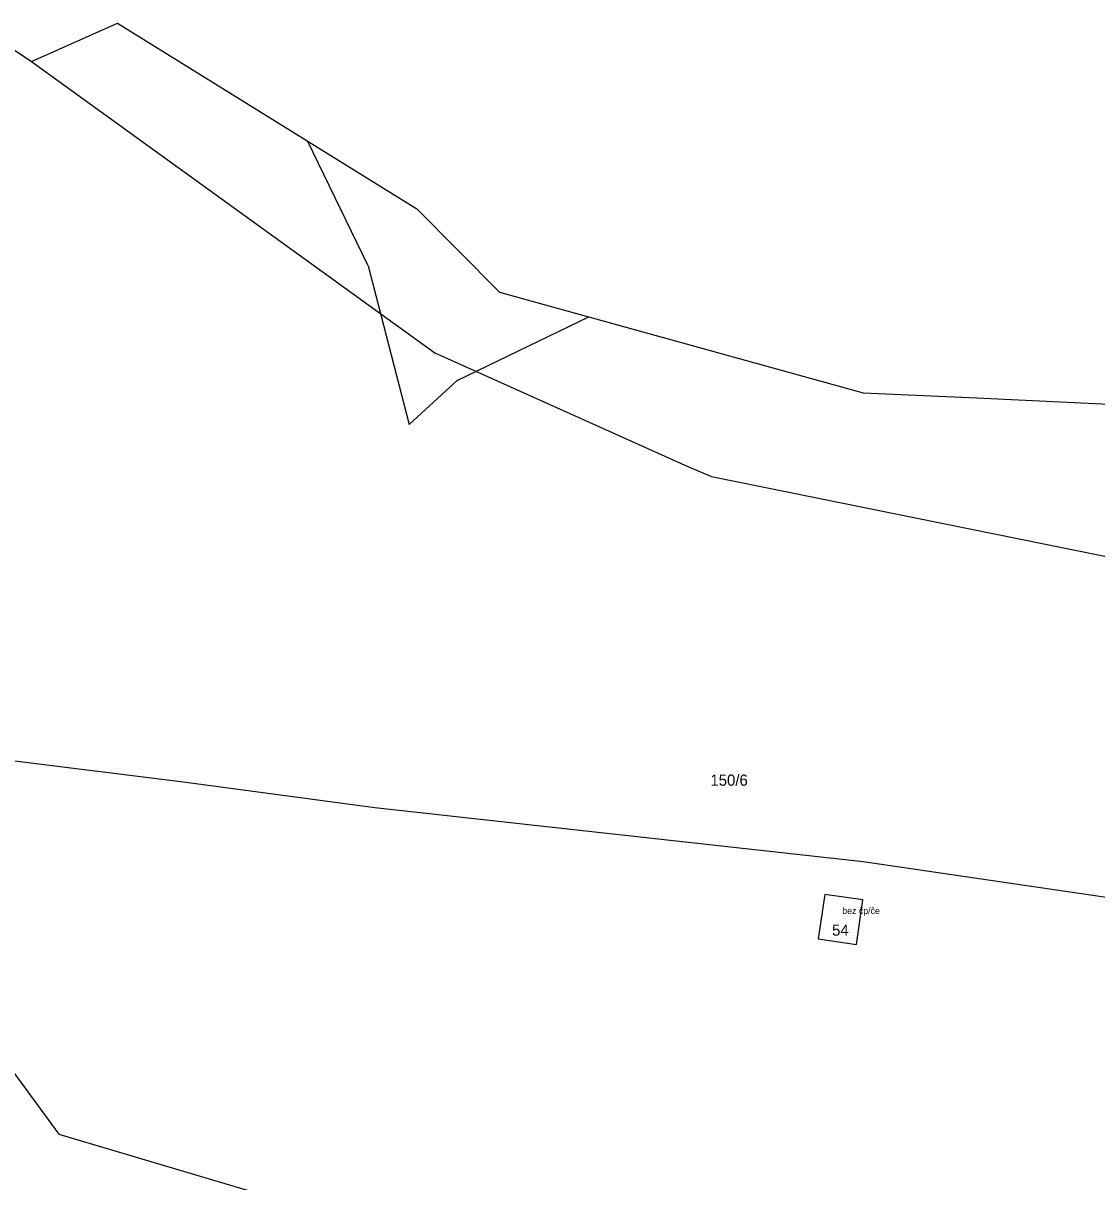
# Model space of a CAD drawing. Extents: x -882150 to -879379, y -1022570 to -1019819.
# Drawn here: x -880484.4 to -880321.1, y -1020139.9 to -1019963.7 of the extents above; entities that cross this region are included whole.
import ezdxf

# ---------------------------------------------------------------- set-up
doc = ezdxf.new("R2010")
doc.units = 0
for name, color, linetype in [('Definiční body', 7, 'Continuous'), ('Hranice parcel', 7, 'Continuous'), ('Parcelní čísla', 7, 'Continuous'), ('Polygon budovy', 7, 'Continuous'), ('Vnitřní kresba', 7, 'Continuous')]:
    doc.layers.add(name, color=color, linetype=linetype)

msp = doc.modelspace()

# ---------------------------------------------------------------- linework, layer by layer
at = {"layer": 'Hranice parcel'}
for p, q in [((-880470.01, -1019963.68), (-880424.53, -1019991.9)), ((-880424.53, -1019991.9), (-880411.97, -1020004.58)), ((-880411.97, -1020004.58), (-880356.66, -1020019.88)), ((-880356.66, -1020019.88), (-880339.38, -1020020.63)), ((-880339.38, -1020020.63), (-880313.53, -1020021.89))]:
    msp.add_line(p, q, dxfattribs=at)
for points in [[(-880490.55, -1019964.56), (-880483.11, -1019969.52), (-880470.01, -1019963.68)], [(-880128.9, -1020103.08), (-880132.45, -1020109.03), (-880189.45, -1020107.84), (-880241.14, -1020104.11), (-880287.51, -1020101.32), (-880356.63, -1020091.22), (-880430.92, -1020082.98), (-880459.65, -1020079.14), (-880540.91, -1020069)], [(-880357.66, -1020103.76), (-880356.68, -1020096.98), (-880362.46, -1020096.17), (-880363.47, -1020102.9), (-880357.66, -1020103.76)], [(-880502.38, -1020102.49), (-880497.06, -1020107.99), (-880478.95, -1020132.59), (-880425.73, -1020148.42), (-880407.16, -1020151.31), (-880349.97, -1020150.48), (-880276.63, -1020134.84)]]:
    msp.add_lwpolyline(points, dxfattribs=at)
at = {"layer": 'Polygon budovy'}
msp.add_lwpolyline([(-880363.47, -1020102.9), (-880357.66, -1020103.76), (-880356.68, -1020096.98), (-880362.46, -1020096.17)], close=True, dxfattribs=at)
at = {"layer": 'Vnitřní kresba'}
for p, q in [((-880483.11, -1019969.52), (-880421.79, -1020013.78)), ((-880431.93, -1020000.59), (-880441.16, -1019981.58)), ((-880431.93, -1020000.59), (-880425.69, -1020024.68)), ((-880418.3, -1020017.94), (-880398.37, -1020008.34)), ((-880421.79, -1020013.78), (-880383.29, -1020031.1)), ((-880425.69, -1020024.68), (-880418.3, -1020017.93)), ((-880383.29, -1020031.1), (-880379.69, -1020032.59)), ((-880379.69, -1020032.59), (-880311.22, -1020046.5))]:
    msp.add_line(p, q, dxfattribs=at)

# ---------------------------------------------------------------- texts
at = {"layer": 'Definiční body'}
msp.add_text('bez čp/če', height=1, dxfattribs=at).set_placement((-880359.83, -1020099.12))
at = {"layer": 'Parcelní čísla'}
for s, p in [('150/6', (-880379.876, -1020079.63)), ('54', (-880361.38, -1020102.43))]:
    msp.add_text(s, height=1.7, dxfattribs=at).set_placement(p)

doc.saveas('drawing.dxf')
